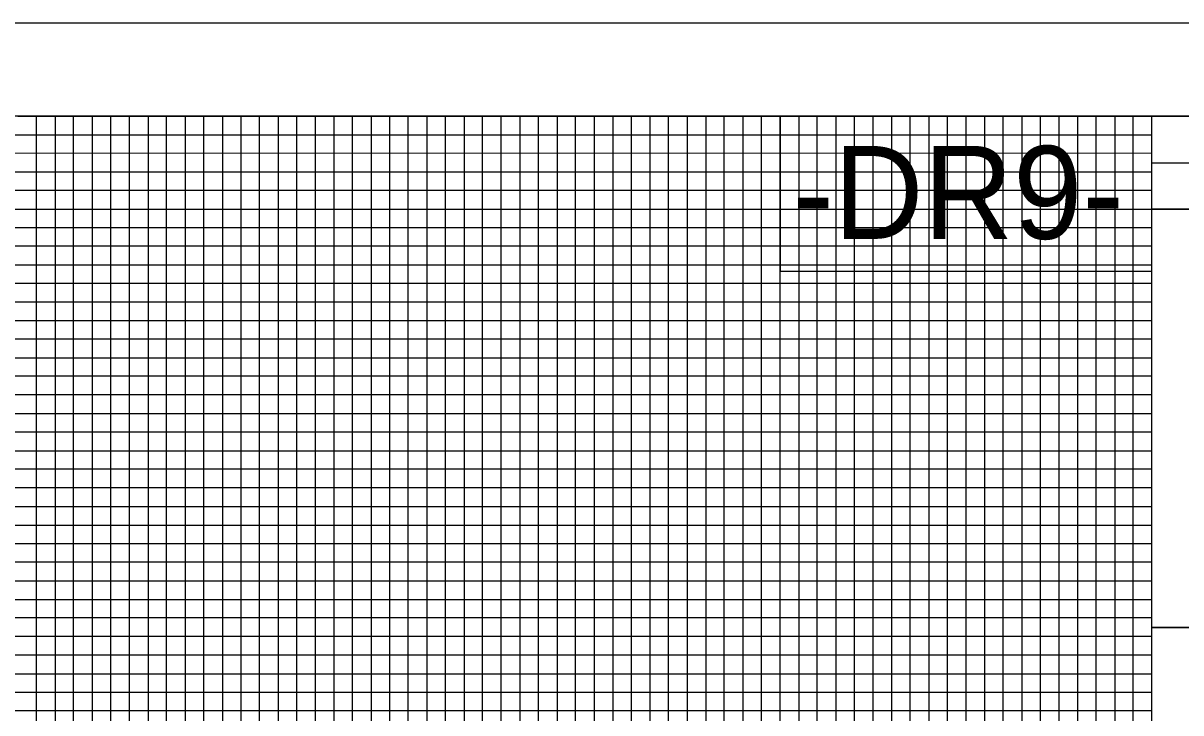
# Model space of a CAD drawing. Extents: x 505602 to 507286, y 483109 to 484209.
# Drawn here: x 506765.5 to 507076.9, y 484023.2 to 484208.7 of the extents above; entities that cross this region are included whole.
import ezdxf

# ---------------------------------------------------------------- set-up
doc = ezdxf.new("R2010")
doc.units = 0
for name, color, linetype in [('Old_Level_1', 7, 'Continuous'), ('Prop Grid Mask', 7, 'Continuous'), ('Sheet Layout Profile Border Port 2', 7, 'Continuous'), ('Sheet Plot Border Outside CELL', 7, 'Continuous'), ('Sheet Profile CELL', 7, 'Continuous'), ('Sheet Profile Grid Major CELL', 7, 'Continuous'), ('Sheet Profile Grid Middle CELL', 7, 'Continuous'), ('Sheet Profile Grid Minor CELL', 7, 'Continuous'), ('Sheet Sticker Exception Certification CELL', 7, 'Continuous')]:
    doc.layers.add(name, color=color, linetype=linetype)

msp = doc.modelspace()

# ---------------------------------------------------------------- linework, layer by layer
at = {"layer": 'Prop Grid Mask'}
msp.add_lwpolyline([(507069.03, 484183.71), (506969.08, 484183.71), (506969.08, 484142), (507069.03, 484142)], close=True, dxfattribs=at)
at = {"layer": 'Sheet Layout Profile Border Port 2'}
msp.add_lwpolyline([(506769.08, 484183.71), (507169.08, 484183.71), (507169.08, 483683.71), (506769.08, 483683.71)], close=True, dxfattribs=at)
at = {"layer": 'Sheet Plot Border Outside CELL'}
msp.add_lwpolyline([(505602.08, 483108.71), (507286.08, 483108.71), (507286.08, 484208.71), (505602.08, 484208.71)], close=True, dxfattribs=at)
at = {"layer": 'Sheet Profile CELL'}
msp.add_line((507069.03, 484171.16), (507269.08, 484171.16), dxfattribs=at)
for points in [[(507269.08, 484183.71), (505769.08, 484183.71), (505769.08, 483133.71), (507269.08, 483133.71)], [(507069.03, 484183.71), (507269.08, 484183.71), (507269.08, 484158.66), (507069.03, 484158.66)], [(507069.03, 484158.66), (507169.08, 484158.66), (507169.08, 484046.16), (507069.03, 484046.16)]]:
    msp.add_lwpolyline(points, close=True, dxfattribs=at)
at = {"layer": 'Sheet Profile Grid Major CELL'}
for points in [[(506719.08, 483683.71), (506769.08, 483683.71), (506769.08, 484183.71), (506819.08, 484183.71), (506819.08, 483683.71), (506869.08, 483683.71), (506869.08, 484183.71), (506919.08, 484183.71), (506919.08, 483683.71), (506969.08, 483683.71), (506969.08, 484183.71), (507019.08, 484183.71), (507019.08, 483683.71), (507069.08, 483683.71), (507069.08, 484183.71), (507095.38, 484183.71)], [(505769.08, 484133.71), (507069.08, 484133.71)], [(507069.08, 484083.71), (505769.08, 484083.71), (505769.08, 484033.71), (507069.08, 484033.71)]]:
    msp.add_lwpolyline(points, dxfattribs=at)
at = {"layer": 'Sheet Profile Grid Middle CELL'}
msp.add_line((505769.08, 484158.71), (507069.03, 484158.71), dxfattribs=at)
msp.add_line((505769.08, 484158.71), (507069.03, 484158.71), dxfattribs=at)
for points in [[(506744.08, 483683.71), (506794.08, 483683.71), (506794.08, 484183.71), (506844.08, 484183.71), (506844.08, 483683.71), (506894.08, 483683.71), (506894.08, 484183.71), (506944.08, 484183.71), (506944.08, 483683.71), (506994.08, 483683.71), (506994.08, 484183.71), (507044.08, 484183.71), (507044.08, 483683.71), (507094.08, 483683.71), (507094.08, 484022.66)], [(507069.08, 484108.71), (505769.08, 484108.71), (505769.08, 484058.71), (507069.08, 484058.71)]]:
    msp.add_lwpolyline(points, dxfattribs=at)
at = {"layer": 'Sheet Profile Grid Minor CELL'}
for p, q in [((505819.08, 484178.71), (507069.08, 484178.71)), ((507069.08, 484173.71), (505819.08, 484173.36)), ((505819.08, 484168.71), (507069.08, 484168.71)), ((507069.03, 484048.71), (505819.08, 484048.71)), ((507069.08, 484043.71), (505819.08, 484043.71)), ((507069.08, 484038.71), (505819.08, 484038.71)), ((505819.08, 484028.71), (507069.08, 484028.71)), ((507069.08, 484023.71), (505819.08, 484023.71))]:
    msp.add_line(p, q, dxfattribs=at)
for points in [[(506764.08, 484183.71), (506774.08, 484183.71), (506774.08, 483683.71)], [(506779.08, 483683.71), (506779.08, 484183.71), (506784.08, 484183.71), (506784.08, 483683.71)], [(506789.08, 483683.71), (506789.08, 484183.71), (506799.08, 484183.71), (506799.08, 483683.71)], [(506804.08, 483683.71), (506804.08, 484183.71), (506809.08, 484183.71), (506809.08, 483683.71)], [(506814.08, 483683.71), (506814.08, 484183.71), (506824.08, 484183.71), (506824.08, 483683.71)], [(506829.08, 483683.71), (506829.08, 484183.71), (506834.08, 484183.71), (506834.08, 483683.71)], [(506839.08, 483683.71), (506839.08, 484183.71), (506849.08, 484183.71), (506849.08, 483683.71)], [(506854.08, 483683.71), (506854.08, 484183.71), (506859.08, 484183.71), (506859.08, 483683.71)], [(506864.08, 483683.71), (506864.08, 484183.71), (506874.08, 484183.71), (506874.08, 483683.71)], [(506879.08, 483683.71), (506879.08, 484183.71), (506884.08, 484183.71), (506884.08, 483683.71)], [(506889.08, 483683.71), (506889.08, 484183.71), (506899.08, 484183.71), (506899.08, 483683.71)], [(506904.08, 483683.71), (506904.08, 484183.71), (506909.08, 484183.71), (506909.08, 483683.71)], [(506914.08, 483683.71), (506914.08, 484183.71), (506924.08, 484183.71), (506924.08, 483683.71)], [(506929.08, 483683.71), (506929.08, 484183.71), (506934.08, 484183.71), (506934.08, 483683.71)], [(506939.08, 483683.71), (506939.08, 484183.71), (506949.08, 484183.71), (506949.08, 483683.71)], [(506954.08, 483683.71), (506954.08, 484183.71), (506959.08, 484183.71), (506959.08, 483683.71)], [(506964.08, 483683.71), (506964.08, 484183.71), (506974.08, 484183.71), (506974.08, 483683.71)], [(506979.08, 483683.71), (506979.08, 484183.71), (506984.08, 484183.71), (506984.08, 483683.71)], [(506989.08, 483683.71), (506989.08, 484183.71), (506999.08, 484183.71), (506999.08, 483683.71)], [(507004.08, 483683.71), (507004.08, 484183.71), (507009.08, 484183.71), (507009.08, 483683.71)], [(507014.08, 483683.71), (507014.08, 484183.71), (507024.08, 484183.71), (507024.08, 483683.71)], [(507029.08, 483683.71), (507029.08, 484183.71), (507034.08, 484183.71), (507034.08, 483683.71)], [(507039.08, 483683.71), (507039.08, 484183.71), (507049.08, 484183.71), (507049.08, 483683.71)], [(507054.08, 483683.71), (507054.08, 484183.71), (507059.08, 484183.71), (507059.08, 483683.71)], [(507064.08, 483683.71), (507064.08, 484183.71), (507074.08, 484183.71)], [(507069.08, 484163.71), (505819.08, 484163.71), (505819.08, 484153.71), (507069.08, 484153.71)], [(507069.03, 484148.71), (505819.08, 484148.71), (505819.08, 484143.71), (507069.08, 484143.71)], [(507069.08, 484138.71), (505819.08, 484138.71), (505819.08, 484128.71), (507069.08, 484128.71)], [(507069.08, 484123.71), (505819.08, 484123.71), (505819.08, 484118.71), (507069.08, 484118.71)], [(507069.08, 484113.71), (505819.08, 484113.71), (505819.08, 484103.71), (507069.08, 484103.71)], [(507069.08, 484098.71), (505819.08, 484098.71), (505819.08, 484093.71), (507069.08, 484093.71)], [(507069.08, 484088.71), (505819.08, 484088.71), (505819.08, 484078.71), (507069.08, 484078.71)], [(507069.08, 484073.61), (505819.18, 484073.61), (505819.18, 484068.71), (507069.08, 484068.71)], [(507069.08, 484063.71), (505819.08, 484063.71), (505819.08, 484053.71), (507069.08, 484053.71)]]:
    msp.add_lwpolyline(points, dxfattribs=at)
at = {"layer": 'Sheet Sticker Exception Certification CELL'}
for p, q in [((507069.03, 484022.66), (507069.03, 484046.16)), ((507069.03, 484046.16), (507269.07, 484046.16)), ((507069.03, 484022.66), (507069.03, 484046.16)), ((507069.03, 484046.16), (507269.07, 484046.16))]:
    msp.add_line(p, q, dxfattribs=at)

# ---------------------------------------------------------------- texts
at = {"layer": 'Old_Level_1'}
msp.add_text('-DR9-', height=25, dxfattribs=at).set_placement((506972.37, 484150.68))

doc.saveas('drawing.dxf')
